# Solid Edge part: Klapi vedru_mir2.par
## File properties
Author: Türk
Template: Iso Part.par
Last saved by: Türk
Revision: 2
Application: Solid Edge
Density: 7833,000 kg/m^3
Accuracy: 0,990
Username: Türk
Material: Steel
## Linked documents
Klapi vedru.par
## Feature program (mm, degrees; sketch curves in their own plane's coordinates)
part copy "CopiedPart_1"
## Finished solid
Body 1: solid body, 3 faces, 2 edges, 0 vertices.
  Faces by surface: plane 2, spline 1
  Edges by curve: intersection 2
Bounding box of the edges (mm; curved faces can reach further): 17.000 x 19.333 x 18.336, from (0, -9.6665, -9.6664) to (17, 9.6667, 8.6699).
Planar faces by outward normal: +x 1, -x 1
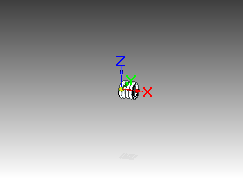
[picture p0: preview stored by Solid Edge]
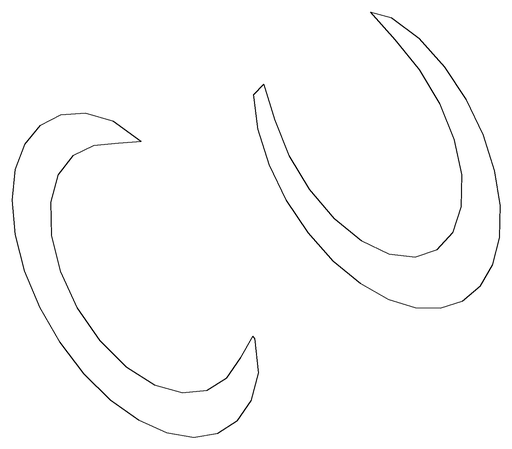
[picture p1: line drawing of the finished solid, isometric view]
